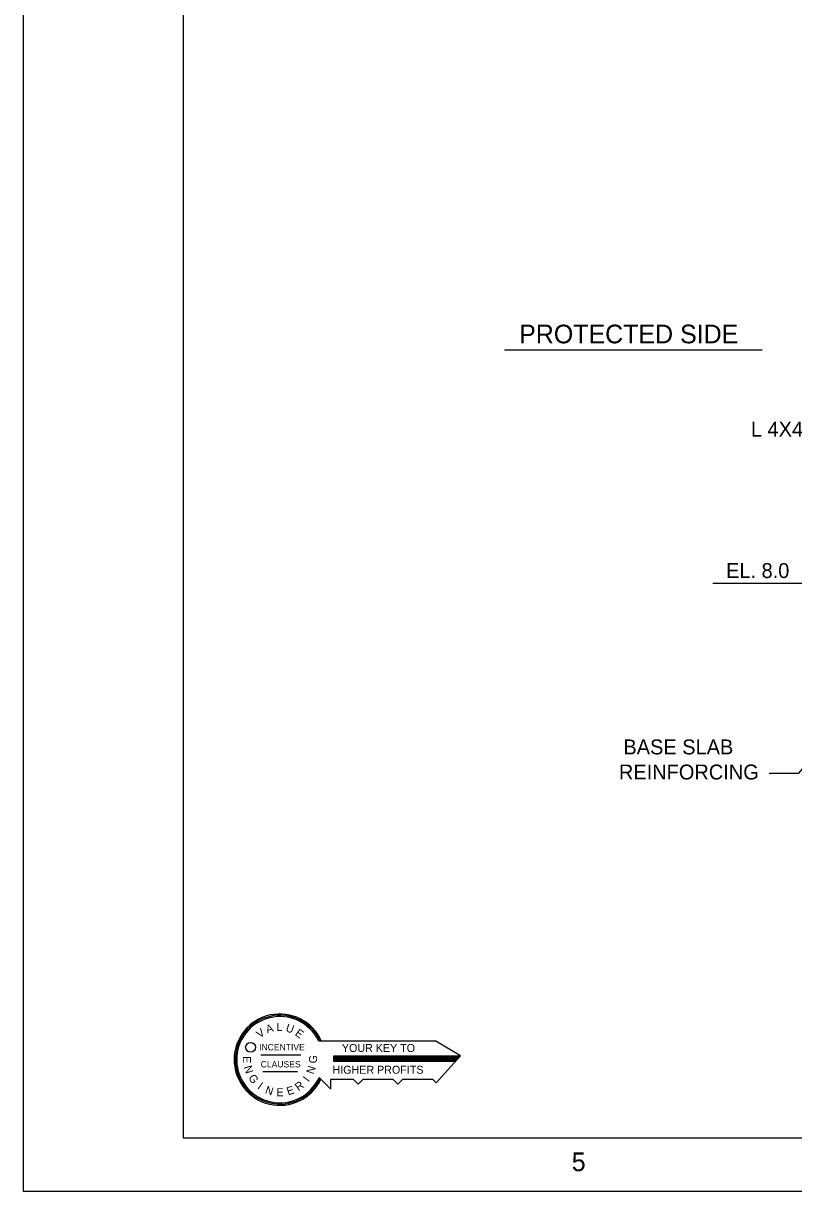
# Model space of a CAD drawing. Extents: x 0 to 320, y -4 to 473.
# Drawn here: x 0 to 7.22, y 0 to 10.95 of the extents above; entities that cross this region are included whole.
import ezdxf

# ---------------------------------------------------------------- set-up
doc = ezdxf.new("R2010")
doc.units = 0
for name, color, linetype in [('Level 1', 7, 'Continuous'), ('Level 3', 7, 'Continuous'), ('Level 44', 7, 'Continuous'), ('Level 50', 7, 'Continuous')]:
    doc.layers.add(name, color=color, linetype=linetype)

msp = doc.modelspace()

# ---------------------------------------------------------------- linework, layer by layer
at = {"layer": 'Level 1'}
for p, q in [((2.766, 1.414), (3.859, 1.414)), ((4.097, 1.273), (3.859, 1.414)), ((2.226, 1.283), (2.6, 1.283)), ((4.094, 1.27), (2.905, 1.27)), ((2.905, 1.27), (2.905, 1.223)), ((4.082, 1.257), (2.905, 1.257)), ((4.072, 1.245), (2.905, 1.245)), ((4.06, 1.232), (2.905, 1.232)), ((2.905, 1.223), (4.052, 1.223)), ((4.097, 1.273), (3.87, 1.019)), ((2.245, 1.125), (2.569, 1.125)), ((2.771, 1.069), (2.88, 0.961)), ((2.88, 0.961), (2.88, 1.054)), ((2.88, 1.054), (3.091, 1.054)), ((3.091, 1.054), (3.137, 1.008)), ((3.137, 1.008), (3.184, 1.054)), ((3.184, 1.054), (3.463, 1.054)), ((3.463, 1.054), (3.509, 1.008)), ((3.509, 1.008), (3.556, 1.054)), ((3.556, 1.054), (3.835, 1.054)), ((3.835, 1.054), (3.87, 1.019))]:
    msp.add_line(p, q, dxfattribs=at)
for points in [[(0, 28), (40, 28), (40, 0), (0, 0)], [(1.5, 27.5), (39.5, 27.5), (39.5, 0.5), (1.5, 0.5)]]:
    msp.add_lwpolyline(points, close=True, dxfattribs=at)
msp.add_circle((2.129, 1.353), 0.0461, dxfattribs=at)
for radius, start, end in [(0.428, 24.569, 334.4243), (0.416, 25.3095, 334.4522), (0.404, 26.0896, 335.5943)]:
    msp.add_arc((2.403, 1.237), radius, start, end, dxfattribs=at)
at = {"layer": 'Level 3'}
msp.add_line((4.509, 7.889), (6.923, 7.889), dxfattribs=at)
msp.add_lwpolyline([(6.989, 3.923), (7.266, 3.923), (8.333, 5.16)], dxfattribs=at)
at = {"layer": 'Level 44'}
msp.add_line((6.462, 5.703), (7.488, 5.703), dxfattribs=at)

# ---------------------------------------------------------------- texts
at = {"layer": 'Level 1'}
for s, rotation, p in [('V', 35.9204, (2.216, 1.435)), ('A', 18.0731, (2.286, 1.483)), ('U', 342.1107, (2.453, 1.504)), ('E', 323.9298, (2.539, 1.471)), ('E', 270, (2.057, 1.27)), ('G', 90, (2.752, 1.202)), ('N', 288.0821, (2.065, 1.168)), ('N', 71.9179, (2.719, 1.096)), ('G', 306.0537, (2.104, 1.066)), ('I', 323.5836, (2.187, 0.97)), ('N', 341.9179, (2.26, 0.923)), ('E', 18.2241, (2.481, 0.902)), ('R', 36.2206, (2.579, 0.94)), ('I', 53.5836, (2.672, 1.023))]:
    msp.add_text(s, height=0.075, rotation=rotation, dxfattribs=at).set_placement(p)
for s, height, p in [('L', 0.075, (2.372, 1.507)), ('INCENTIVE', 0.06, (2.209, 1.324)), ('YOUR KEY TO', 0.075, (2.985, 1.309)), ('CLAUSES', 0.06, (2.224, 1.164)), ('HIGHER PROFITS', 0.075, (2.897, 1.105)), ('E', 0.075, (2.371, 0.894)), ('5', 0.175, (5.139, 0.192))]:
    msp.add_text(s, height=height, dxfattribs=at).set_placement(p)
at = {"layer": 'Level 3'}
msp.add_text('PROTECTED SIDE', height=0.17497, dxfattribs=at).set_placement((4.646, 7.951))
at = {"layer": 'Level 44'}
msp.add_text('L 4X4X…', height=0.14, dxfattribs=at).set_placement((6.818, 7.077))
at = {"layer": 'Level 50'}
for s, height, p in [('EL. 8.0', 0.14, (6.585, 5.751)), ('BASE SLAB', 0.14, (5.623, 4.098)), ('REINFORCING', 0.14002, (5.581, 3.863))]:
    msp.add_text(s, height=height, dxfattribs=at).set_placement(p)

doc.saveas('drawing.dxf')
